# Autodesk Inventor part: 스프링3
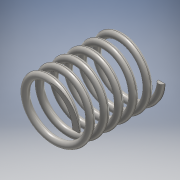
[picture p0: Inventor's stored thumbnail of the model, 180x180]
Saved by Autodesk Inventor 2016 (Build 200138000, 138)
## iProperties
Created: 2019-07
Part Number: 스프링3
Material: 강철, 탄소
Document SubType Name: Modeling
Designer: 602-01
Density: 7.85 g/cm^3
Appearance: 반연마
Mass: 7.77017 g
Surface Area: 20.0872 cm^2
Volume: 0.989831 cm^3
Author: 602-01
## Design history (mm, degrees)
sketch "스케치1"
  geometry: L1 (0, 0)-(8.5, 0); L2 (8.5, 0)-(8.5, 16.67); L3 (8.5, 16.67)-(0, 16.67); L4 (0, 16.67)-(0, 0); C1 r 1 at (8.5, 0)
  constraints: 8 end point, 2 parallel, 1 centre point, 1 coincident, 1 horizontal, 1 perpendicular
  dimensions: "d0" = 17 diameter of L2 L4; "d1" = 16.66987 distance between parallel lines of L1 L3 (derived); "d2" = 2 diameter of C1
feature "코일1" sketch "스케치1" pitch "d3" = 10; turns "d5" = 6; dims "d4" = 16.66987 (= d1), "d6" = 0, angle "d7" = 90 deg, angle "d8" = 90 deg, "d9" = 0, "d10" = 0
sketch "스케치2"
  geometry: L1 (-7.5, 0)-(-9.5, 0) reference; 1 further point
  constraints: 1 horizontal alignment
extrude "돌출1" cut sketch "스케치2" distance "d11" = 10; taper "d12" = 0 deg
node "작업 평면1"
sketch "스케치3"
  geometry: L1 (-1, 0)-(1, 0) reference; 1 further point
  constraints: 1 horizontal alignment
extrude "돌출2" cut sketch "스케치3" distance "d14" = 10; taper "d15" = 0 deg
node "솔리드1"
node "절단 모서리 투영1"
node "절단 모서리 투영2"
other parameters: "d13" = 90 deg
